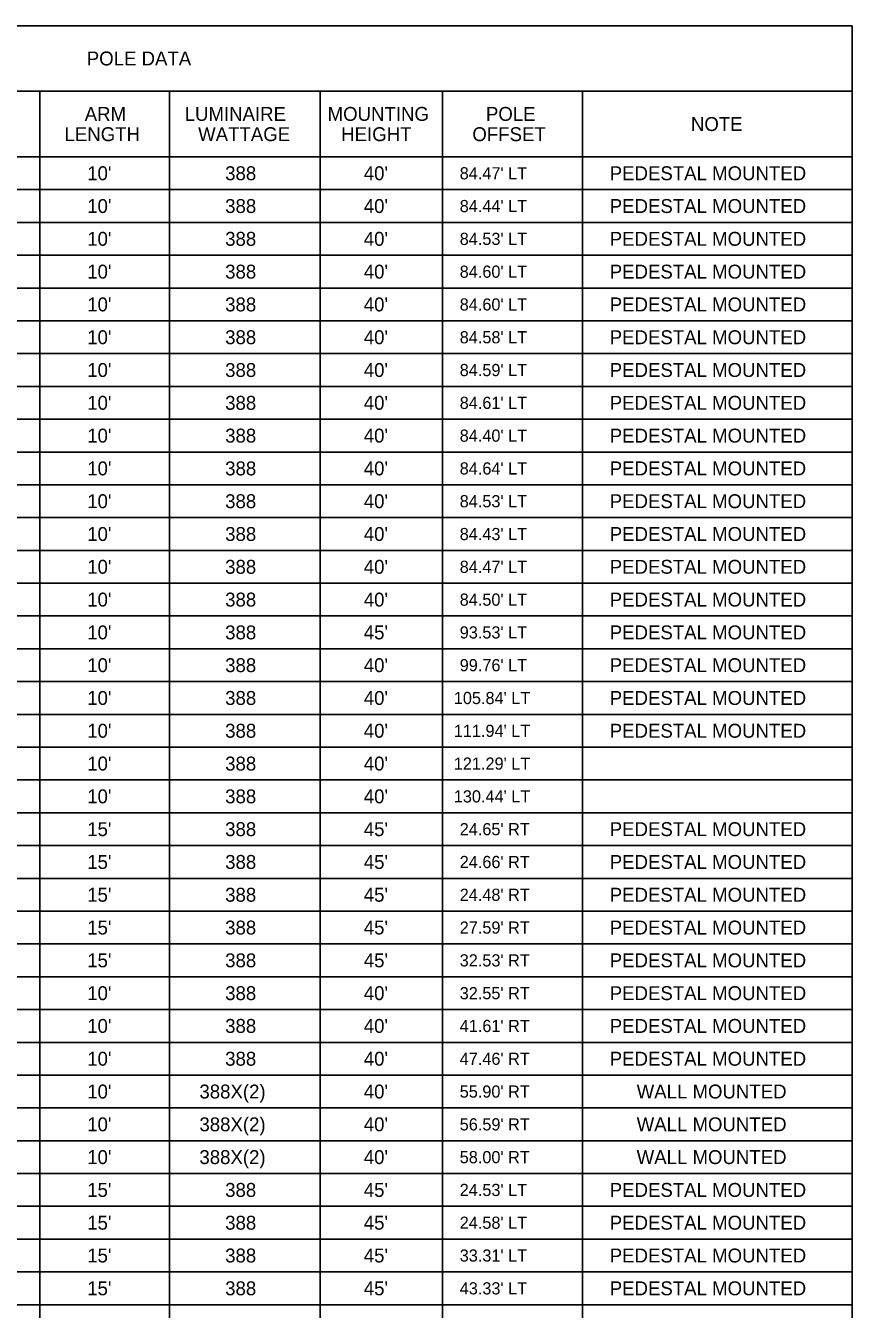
# Model space of a CAD drawing. Extents: x -818.1 to -802.4, y -2198.1 to -2187.9.
# Drawn here: x -814.27 to -810.11, y -2194.32 to -2187.86 of the extents above; entities that cross this region are included whole.
import ezdxf

# ---------------------------------------------------------------- set-up
doc = ezdxf.new("R2010")
doc.units = 0
for name, color, linetype in [('SumBoxBorder_dp', 7, 'Continuous'), ('SumBoxLines_dp', 7, 'Continuous'), ('SumBoxLinesMin_dp', 7, 'Continuous'), ('TextLabel', 7, 'Continuous')]:
    doc.layers.add(name, color=color, linetype=linetype)

msp = doc.modelspace()

# ---------------------------------------------------------------- linework, layer by layer
at = {"layer": 'SumBoxBorder_dp'}
for p, q in [((-817.2394, -2187.8581), (-810.1144, -2187.8581)), ((-810.1144, -2187.8581), (-810.1144, -2195.9431)), ((-810.1144, -2187.8581), (-810.1144, -2195.9431)), ((-817.2394, -2188.1881), (-810.1144, -2188.1881)), ((-817.2394, -2188.1881), (-810.1144, -2188.1881))]:
    msp.add_line(p, q, dxfattribs=at)
at = {"layer": 'SumBoxLines_dp'}
for p, q in [((-814.2019, -2188.1881), (-814.2019, -2193.9631)), ((-814.2019, -2188.1881), (-814.2019, -2195.9431)), ((-813.5494, -2188.1881), (-813.5494, -2195.9431)), ((-813.5494, -2188.1881), (-813.5494, -2195.9431)), ((-812.7919, -2188.1881), (-812.7919, -2195.9431)), ((-812.7919, -2188.1881), (-812.7919, -2195.9431)), ((-812.1769, -2188.1881), (-812.1769, -2194.2931)), ((-812.1769, -2188.1881), (-812.1769, -2195.9431)), ((-811.4719, -2188.1881), (-811.4719, -2195.6131)), ((-811.4719, -2188.1881), (-811.4719, -2195.9431)), ((-817.2394, -2188.5181), (-810.1144, -2188.5181)), ((-814.2019, -2194.1281), (-814.2019, -2195.6131))]:
    msp.add_line(p, q, dxfattribs=at)
at = {"layer": 'SumBoxLinesMin_dp'}
for p, q in [((-817.2394, -2188.5181), (-810.1144, -2188.5181)), ((-817.2394, -2188.6831), (-810.1144, -2188.6831)), ((-817.2394, -2188.6831), (-810.1144, -2188.6831)), ((-817.2394, -2188.8481), (-810.1144, -2188.8481)), ((-817.2394, -2188.8481), (-810.1144, -2188.8481)), ((-817.2394, -2189.0131), (-810.1144, -2189.0131)), ((-817.2394, -2189.0131), (-810.1144, -2189.0131)), ((-817.2394, -2189.1781), (-810.1144, -2189.1781)), ((-817.2394, -2189.1781), (-810.1144, -2189.1781)), ((-817.2394, -2189.3431), (-810.1144, -2189.3431)), ((-817.2394, -2189.3431), (-810.1144, -2189.3431)), ((-817.2394, -2189.5081), (-810.1144, -2189.5081)), ((-817.2394, -2189.5081), (-810.1144, -2189.5081)), ((-817.2394, -2189.6731), (-810.1144, -2189.6731)), ((-817.2394, -2189.6731), (-810.1144, -2189.6731)), ((-817.2394, -2189.8381), (-810.1144, -2189.8381)), ((-817.2394, -2189.8381), (-810.1144, -2189.8381)), ((-817.2394, -2190.0031), (-810.1144, -2190.0031)), ((-817.2394, -2190.0031), (-810.1144, -2190.0031)), ((-817.2394, -2190.1681), (-810.1144, -2190.1681)), ((-817.2394, -2190.1681), (-810.1144, -2190.1681)), ((-817.2394, -2190.3331), (-810.1144, -2190.3331)), ((-817.2394, -2190.3331), (-810.1144, -2190.3331)), ((-817.2394, -2190.4981), (-810.1144, -2190.4981)), ((-817.2394, -2190.4981), (-810.1144, -2190.4981)), ((-817.2394, -2190.6631), (-810.1144, -2190.6631)), ((-817.2394, -2190.6631), (-810.1144, -2190.6631)), ((-817.2394, -2190.8281), (-810.1144, -2190.8281)), ((-817.2394, -2190.8281), (-810.1144, -2190.8281)), ((-817.2394, -2190.9931), (-810.1144, -2190.9931)), ((-817.2394, -2190.9931), (-810.1144, -2190.9931)), ((-817.2394, -2191.1581), (-810.1144, -2191.1581)), ((-817.2394, -2191.1581), (-810.1144, -2191.1581)), ((-817.2394, -2191.3231), (-810.1144, -2191.3231)), ((-817.2394, -2191.3231), (-810.1144, -2191.3231)), ((-817.2394, -2191.4881), (-810.1144, -2191.4881)), ((-817.2394, -2191.4881), (-810.1144, -2191.4881)), ((-817.2394, -2191.6531), (-810.1144, -2191.6531)), ((-817.2394, -2191.6531), (-810.1144, -2191.6531)), ((-817.2394, -2191.8181), (-810.1144, -2191.8181)), ((-817.2394, -2191.8181), (-810.1144, -2191.8181)), ((-817.2394, -2191.9831), (-810.1144, -2191.9831)), ((-817.2394, -2191.9831), (-810.1144, -2191.9831)), ((-817.2394, -2192.1481), (-810.1144, -2192.1481)), ((-817.2394, -2192.1481), (-810.1144, -2192.1481)), ((-817.2394, -2192.3131), (-810.1144, -2192.3131)), ((-817.2394, -2192.3131), (-810.1144, -2192.3131)), ((-817.2394, -2192.4781), (-810.1144, -2192.4781)), ((-817.2394, -2192.4781), (-810.1144, -2192.4781)), ((-817.2394, -2192.6431), (-810.1144, -2192.6431)), ((-817.2394, -2192.6431), (-810.1144, -2192.6431)), ((-817.2394, -2192.8081), (-810.1144, -2192.8081)), ((-817.2394, -2192.8081), (-810.1144, -2192.8081)), ((-817.2394, -2192.9731), (-810.1144, -2192.9731)), ((-817.2394, -2192.9731), (-810.1144, -2192.9731)), ((-817.2394, -2193.1381), (-810.1144, -2193.1381)), ((-817.2394, -2193.1381), (-810.1144, -2193.1381)), ((-817.2394, -2193.3031), (-810.1144, -2193.3031)), ((-817.2394, -2193.3031), (-810.1144, -2193.3031)), ((-817.2394, -2193.4681), (-810.1144, -2193.4681)), ((-817.2394, -2193.4681), (-810.1144, -2193.4681)), ((-817.2394, -2193.6331), (-810.1144, -2193.6331)), ((-817.2394, -2193.6331), (-810.1144, -2193.6331)), ((-817.2394, -2193.7981), (-810.1144, -2193.7981)), ((-817.2394, -2193.7981), (-810.1144, -2193.7981)), ((-817.2394, -2193.9631), (-810.1144, -2193.9631)), ((-817.2394, -2193.9631), (-810.1144, -2193.9631)), ((-817.2394, -2194.1281), (-810.1144, -2194.1281)), ((-814.2019, -2194.1281), (-810.1144, -2194.1281)), ((-817.2394, -2194.2931), (-810.1144, -2194.2931)), ((-817.2394, -2194.2931), (-810.1144, -2194.2931))]:
    msp.add_line(p, q, dxfattribs=at)

# ---------------------------------------------------------------- texts
at = {"layer": 'TextLabel'}
for s, height, p in [('POLE DATA', 0.07, (-813.9658, -2188.0581)), ('ARM', 0.07, (-813.9762, -2188.3371)), ('LUMINAIRE', 0.07, (-813.4733, -2188.3371)), ('MOUNTING', 0.07, (-812.7541, -2188.3371)), ('POLE', 0.07, (-811.9577, -2188.3371)), ('LENGTH', 0.07, (-814.0776, -2188.4391)), ('WATTAGE', 0.07, (-813.4056, -2188.4391)), ('HEIGHT', 0.07, (-812.6859, -2188.4391)), ('OFFSET', 0.07, (-812.0259, -2188.4391)), ('NOTE', 0.07, (-810.9264, -2188.3881)), ("10'", 0.07, (-813.9636, -2188.6356)), ('388', 0.07, (-813.2696, -2188.6356)), ("40'", 0.07, (-812.5723, -2188.6356)), ("84.47' LT", 0.06125, (-812.0896, -2188.6313)), ('PEDESTAL MOUNTED', 0.07, (-811.3349, -2188.6356)), ("10'", 0.07, (-813.9636, -2188.8006)), ('388', 0.07, (-813.2696, -2188.8006)), ("40'", 0.07, (-812.5723, -2188.8006)), ("84.44' LT", 0.06125, (-812.0896, -2188.7963)), ('PEDESTAL MOUNTED', 0.07, (-811.3349, -2188.8006)), ("10'", 0.07, (-813.9636, -2188.9656)), ('388', 0.07, (-813.2696, -2188.9656)), ("40'", 0.07, (-812.5723, -2188.9656)), ("84.53' LT", 0.06125, (-812.0896, -2188.9613)), ('PEDESTAL MOUNTED', 0.07, (-811.3349, -2188.9656)), ("10'", 0.07, (-813.9636, -2189.1306)), ('388', 0.07, (-813.2696, -2189.1306)), ("40'", 0.07, (-812.5723, -2189.1306)), ("84.60' LT", 0.06125, (-812.0896, -2189.1263)), ('PEDESTAL MOUNTED', 0.07, (-811.3349, -2189.1306)), ("10'", 0.07, (-813.9636, -2189.2956)), ('388', 0.07, (-813.2696, -2189.2956)), ("40'", 0.07, (-812.5723, -2189.2956)), ("84.60' LT", 0.06125, (-812.0896, -2189.2913)), ('PEDESTAL MOUNTED', 0.07, (-811.3349, -2189.2956)), ("10'", 0.07, (-813.9636, -2189.4606)), ('388', 0.07, (-813.2696, -2189.4606)), ("40'", 0.07, (-812.5723, -2189.4606)), ("84.58' LT", 0.06125, (-812.0896, -2189.4563)), ('PEDESTAL MOUNTED', 0.07, (-811.3349, -2189.4606)), ("10'", 0.07, (-813.9636, -2189.6256)), ('388', 0.07, (-813.2696, -2189.6256)), ("40'", 0.07, (-812.5723, -2189.6256)), ("84.59' LT", 0.06125, (-812.0896, -2189.6213)), ('PEDESTAL MOUNTED', 0.07, (-811.3349, -2189.6256)), ("10'", 0.07, (-813.9636, -2189.7906)), ('388', 0.07, (-813.2696, -2189.7906)), ("40'", 0.07, (-812.5723, -2189.7906)), ("84.61' LT", 0.06125, (-812.0896, -2189.7863)), ('PEDESTAL MOUNTED', 0.07, (-811.3349, -2189.7906)), ("10'", 0.07, (-813.9636, -2189.9556)), ('388', 0.07, (-813.2696, -2189.9556)), ("40'", 0.07, (-812.5723, -2189.9556)), ("84.40' LT", 0.06125, (-812.0896, -2189.9513)), ('PEDESTAL MOUNTED', 0.07, (-811.3349, -2189.9556)), ("10'", 0.07, (-813.9636, -2190.1206)), ('388', 0.07, (-813.2696, -2190.1206)), ("40'", 0.07, (-812.5723, -2190.1206)), ('PEDESTAL MOUNTED', 0.07, (-811.3349, -2190.1206)), ("84.64' LT", 0.06125, (-812.0896, -2190.1163)), ("10'", 0.07, (-813.9636, -2190.2856)), ('388', 0.07, (-813.2696, -2190.2856)), ("40'", 0.07, (-812.5723, -2190.2856)), ("84.53' LT", 0.06125, (-812.0896, -2190.2813)), ('PEDESTAL MOUNTED', 0.07, (-811.3349, -2190.2856)), ("10'", 0.07, (-813.9636, -2190.4506)), ('388', 0.07, (-813.2696, -2190.4506)), ("40'", 0.07, (-812.5723, -2190.4506)), ("84.43' LT", 0.06125, (-812.0896, -2190.4463)), ('PEDESTAL MOUNTED', 0.07, (-811.3349, -2190.4506)), ("10'", 0.07, (-813.9636, -2190.6156)), ('388', 0.07, (-813.2696, -2190.6156)), ("40'", 0.07, (-812.5723, -2190.6156)), ("84.47' LT", 0.06125, (-812.0896, -2190.6113)), ('PEDESTAL MOUNTED', 0.07, (-811.3349, -2190.6156)), ("10'", 0.07, (-813.9636, -2190.7806)), ('388', 0.07, (-813.2696, -2190.7806)), ("40'", 0.07, (-812.5723, -2190.7806)), ("84.50' LT", 0.06125, (-812.0896, -2190.7763)), ('PEDESTAL MOUNTED', 0.07, (-811.3349, -2190.7806)), ("10'", 0.07, (-813.9636, -2190.9456)), ('388', 0.07, (-813.2696, -2190.9456)), ("45'", 0.07, (-812.5723, -2190.9456)), ("93.53' LT", 0.06125, (-812.0896, -2190.9413)), ('PEDESTAL MOUNTED', 0.07, (-811.3349, -2190.9456)), ("10'", 0.07, (-813.9636, -2191.1106)), ('388', 0.07, (-813.2696, -2191.1106)), ("40'", 0.07, (-812.5723, -2191.1106)), ("99.76' LT", 0.06125, (-812.0896, -2191.1063)), ('PEDESTAL MOUNTED', 0.07, (-811.3349, -2191.1106)), ("10'", 0.07, (-813.9636, -2191.2756)), ('388', 0.07, (-813.2696, -2191.2756)), ("40'", 0.07, (-812.5723, -2191.2756)), ("105.84' LT", 0.06125, (-812.1193, -2191.2713)), ('PEDESTAL MOUNTED', 0.07, (-811.3349, -2191.2756)), ("10'", 0.07, (-813.9636, -2191.4406)), ('388', 0.07, (-813.2696, -2191.4406)), ("40'", 0.07, (-812.5723, -2191.4406)), ("111.94' LT", 0.06125, (-812.1193, -2191.4363)), ('PEDESTAL MOUNTED', 0.07, (-811.3349, -2191.4406)), ("10'", 0.07, (-813.9636, -2191.6056)), ('388', 0.07, (-813.2696, -2191.6056)), ("40'", 0.07, (-812.5723, -2191.6056)), ("121.29' LT", 0.06125, (-812.1193, -2191.6013)), ("10'", 0.07, (-813.9636, -2191.7706)), ('388', 0.07, (-813.2696, -2191.7706)), ("40'", 0.07, (-812.5723, -2191.7706)), ("130.44' LT", 0.06125, (-812.1193, -2191.7663)), ("15'", 0.07, (-813.9636, -2191.9356)), ('388', 0.07, (-813.2696, -2191.9356)), ("45'", 0.07, (-812.5723, -2191.9356)), ("24.65' RT", 0.06125, (-812.0896, -2191.9313)), ('PEDESTAL MOUNTED', 0.07, (-811.3349, -2191.9356)), ("15'", 0.07, (-813.9636, -2192.1006)), ('388', 0.07, (-813.2696, -2192.1006)), ("45'", 0.07, (-812.5723, -2192.1006)), ("24.66' RT", 0.06125, (-812.0896, -2192.0963)), ('PEDESTAL MOUNTED', 0.07, (-811.3349, -2192.1006)), ("15'", 0.07, (-813.9636, -2192.2656)), ('388', 0.07, (-813.2696, -2192.2656)), ("45'", 0.07, (-812.5723, -2192.2656)), ("24.48' RT", 0.06125, (-812.0896, -2192.2613)), ('PEDESTAL MOUNTED', 0.07, (-811.3349, -2192.2656)), ("15'", 0.07, (-813.9636, -2192.4306)), ('388', 0.07, (-813.2696, -2192.4306)), ("45'", 0.07, (-812.5723, -2192.4306)), ("27.59' RT", 0.06125, (-812.0896, -2192.4263)), ('PEDESTAL MOUNTED', 0.07, (-811.3349, -2192.4306)), ("15'", 0.07, (-813.9636, -2192.5956)), ('388', 0.07, (-813.2696, -2192.5956)), ("45'", 0.07, (-812.5723, -2192.5956)), ("32.53' RT", 0.06125, (-812.0896, -2192.5913)), ('PEDESTAL MOUNTED', 0.07, (-811.3349, -2192.5956)), ("10'", 0.07, (-813.9636, -2192.7606)), ('388', 0.07, (-813.2696, -2192.7606)), ("40'", 0.07, (-812.5723, -2192.7606)), ("32.55' RT", 0.06125, (-812.0896, -2192.7563)), ('PEDESTAL MOUNTED', 0.07, (-811.3349, -2192.7606)), ("10'", 0.07, (-813.9636, -2192.9256)), ('388', 0.07, (-813.2696, -2192.9256)), ("40'", 0.07, (-812.5723, -2192.9256)), ("41.61' RT", 0.06125, (-812.0896, -2192.9213)), ('PEDESTAL MOUNTED', 0.07, (-811.3349, -2192.9256)), ("10'", 0.07, (-813.9636, -2193.0906)), ('388', 0.07, (-813.2696, -2193.0906)), ("40'", 0.07, (-812.5723, -2193.0906)), ('PEDESTAL MOUNTED', 0.07, (-811.3349, -2193.0906)), ("47.46' RT", 0.06125, (-812.0896, -2193.0863)), ("10'", 0.07, (-813.9636, -2193.2556)), ('388X(2)', 0.07, (-813.3991, -2193.2556)), ("40'", 0.07, (-812.5723, -2193.2556)), ("55.90' RT", 0.06125, (-812.0896, -2193.2513)), ('WALL MOUNTED', 0.07, (-811.1994, -2193.2556)), ("10'", 0.07, (-813.9636, -2193.4206)), ('388X(2)', 0.07, (-813.3991, -2193.4206)), ("40'", 0.07, (-812.5723, -2193.4206)), ("56.59' RT", 0.06125, (-812.0896, -2193.4163)), ('WALL MOUNTED', 0.07, (-811.1994, -2193.4206)), ("10'", 0.07, (-813.9636, -2193.5856)), ('388X(2)', 0.07, (-813.3991, -2193.5856)), ("40'", 0.07, (-812.5723, -2193.5856)), ("58.00' RT", 0.06125, (-812.0896, -2193.5813)), ('WALL MOUNTED', 0.07, (-811.1994, -2193.5856)), ("15'", 0.07, (-813.9636, -2193.7506)), ('388', 0.07, (-813.2696, -2193.7506)), ("45'", 0.07, (-812.5723, -2193.7506)), ("24.53' LT", 0.06125, (-812.0896, -2193.7463)), ('PEDESTAL MOUNTED', 0.07, (-811.3349, -2193.7506)), ("15'", 0.07, (-813.9636, -2193.9156)), ('388', 0.07, (-813.2696, -2193.9156)), ("45'", 0.07, (-812.5723, -2193.9156)), ("24.58' LT", 0.06125, (-812.0896, -2193.9113)), ('PEDESTAL MOUNTED', 0.07, (-811.3349, -2193.9156)), ("15'", 0.07, (-813.9636, -2194.0806)), ('388', 0.07, (-813.2696, -2194.0806)), ("45'", 0.07, (-812.5723, -2194.0806)), ("33.31' LT", 0.06125, (-812.0896, -2194.0763)), ('PEDESTAL MOUNTED', 0.07, (-811.3349, -2194.0806)), ("15'", 0.07, (-813.9636, -2194.2456)), ('388', 0.07, (-813.2696, -2194.2456)), ("45'", 0.07, (-812.5723, -2194.2456)), ("43.33' LT", 0.06125, (-812.0896, -2194.2413)), ('PEDESTAL MOUNTED', 0.07, (-811.3349, -2194.2456))]:
    msp.add_text(s, height=height, dxfattribs=at).set_placement(p)

doc.saveas('drawing.dxf')
